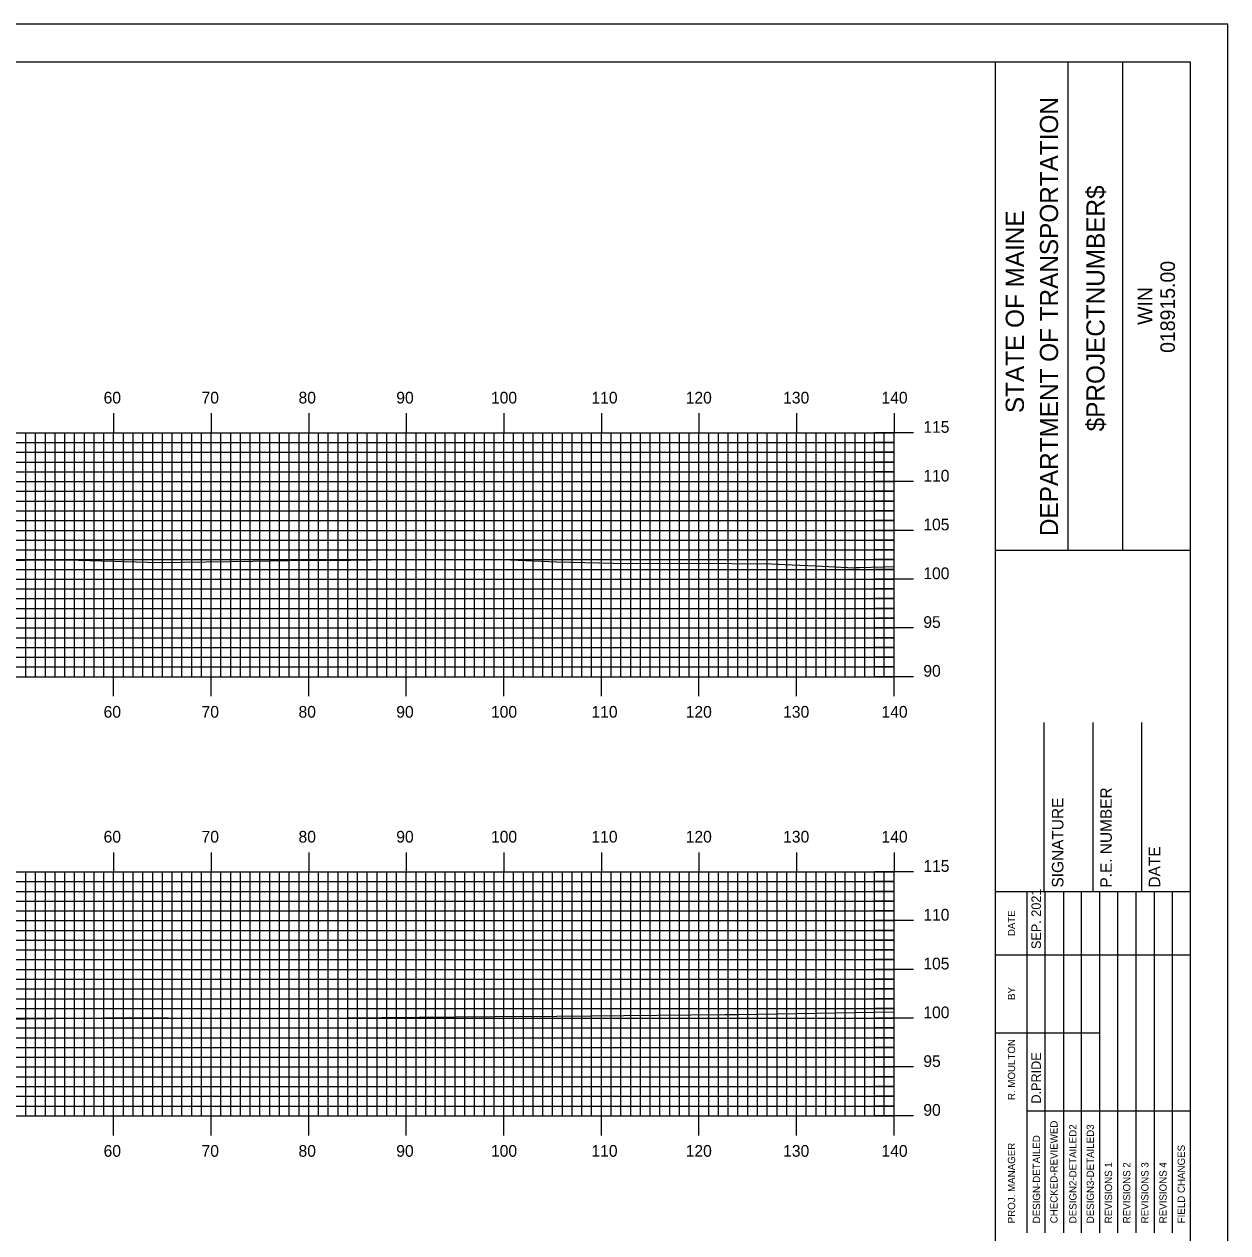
# Model space of a CAD drawing. Extents: x 1765333 to 1765676, y 442591 to 442811.
# Drawn here: x 1765549.2 to 1765672.6, y 442686.7 to 442810.5 of the extents above; entities that cross this region are included whole.
import ezdxf

# ---------------------------------------------------------------- set-up
doc = ezdxf.new("R2010")
doc.units = 0
for name, color, linetype in [('BORDER', 7, 'Continuous'), ('H_V ANNOTATION', 7, 'Continuous'), ('MAJOR', 7, 'Continuous'), ('MINOR', 7, 'Continuous'), ('PLOT BOUNDARY', 7, 'Continuous'), ('S_Roadway_Centerline', 7, 'Continuous')]:
    doc.layers.add(name, color=color, linetype=linetype)

msp = doc.modelspace()

# ---------------------------------------------------------------- linework, layer by layer
at = {"layer": 'BORDER'}
for p, q in [((1765648.77, 442596.67), (1765648.77, 442806.67)), ((1765656.23, 442756.66), (1765656.23, 442806.66)), ((1765661.82, 442756.66), (1765661.82, 442806.66)), ((1765648.77, 442756.65), (1765668.77, 442756.65)), ((1765653.77, 442721.67), (1765653.77, 442738.97)), ((1765658.77, 442721.67), (1765658.77, 442738.97)), ((1765663.77, 442721.67), (1765663.77, 442738.97)), ((1765648.77, 442721.67), (1765668.77, 442721.67))]:
    msp.add_line(p, q, dxfattribs=at)
msp.add_lwpolyline([(1765348.77, 442596.67), (1765668.77, 442596.67), (1765668.77, 442806.67), (1765348.77, 442806.67)], close=True, dxfattribs=at)
for points in [[(1765652, 442715.17), (1765652, 442721.67)], [(1765653.87, 442686.68), (1765653.87, 442721.67)], [(1765655.73, 442721.67), (1765655.73, 442686.68)], [(1765657.59, 442686.68), (1765657.59, 442721.67)], [(1765659.46, 442686.68), (1765659.46, 442721.67)], [(1765661.32, 442686.68), (1765661.32, 442721.67)], [(1765663.18, 442686.68), (1765663.18, 442721.67)], [(1765665.05, 442686.68), (1765665.05, 442721.67)], [(1765666.91, 442686.68), (1765666.91, 442721.67)], [(1765652, 442686.68), (1765652, 442720.26)], [(1765648.77, 442715.17), (1765668.77, 442715.17)], [(1765648.77, 442707.17), (1765652, 442707.17)], [(1765652, 442707.17), (1765659.45, 442707.17)], [(1765652, 442699.17), (1765668.77, 442699.17)]]:
    msp.add_lwpolyline(points, dxfattribs=at)
at = {"layer": 'MAJOR'}
for p, q in [((1765558.37, 442770.67), (1765558.37, 442768.67)), ((1765568.37, 442770.67), (1765568.37, 442768.67)), ((1765578.37, 442770.67), (1765578.37, 442768.67)), ((1765588.37, 442770.67), (1765588.37, 442768.67)), ((1765598.37, 442770.67), (1765598.37, 442768.67)), ((1765608.37, 442770.67), (1765608.37, 442768.67)), ((1765618.37, 442770.67), (1765618.37, 442768.67)), ((1765628.37, 442770.67), (1765628.37, 442768.67)), ((1765638.37, 442770.67), (1765638.37, 442768.67)), ((1765358.37, 442768.67), (1765638.37, 442768.67)), ((1765358.37, 442768.67), (1765638.37, 442768.67)), ((1765558.37, 442743.67), (1765558.37, 442768.67)), ((1765568.37, 442743.67), (1765568.37, 442768.67)), ((1765578.37, 442743.67), (1765578.37, 442768.67)), ((1765588.37, 442743.67), (1765588.37, 442768.67)), ((1765598.37, 442743.67), (1765598.37, 442768.67)), ((1765608.37, 442743.67), (1765608.37, 442768.67)), ((1765618.37, 442743.67), (1765618.37, 442768.67)), ((1765628.37, 442743.67), (1765628.37, 442768.67)), ((1765640.37, 442768.67), (1765636.37, 442768.67)), ((1765638.37, 442743.67), (1765638.37, 442768.67)), ((1765638.37, 442743.67), (1765638.37, 442768.67)), ((1765358.37, 442763.67), (1765638.37, 442763.67)), ((1765640.37, 442763.67), (1765636.37, 442763.67)), ((1765358.37, 442758.67), (1765638.37, 442758.67)), ((1765640.37, 442758.67), (1765636.37, 442758.67)), ((1765358.37, 442753.67), (1765638.37, 442753.67)), ((1765640.37, 442753.67), (1765636.37, 442753.67)), ((1765358.37, 442748.67), (1765638.37, 442748.67)), ((1765640.37, 442748.67), (1765636.37, 442748.67)), ((1765358.37, 442743.67), (1765638.37, 442743.67)), ((1765358.37, 442743.67), (1765638.37, 442743.67)), ((1765558.37, 442741.66), (1765558.37, 442743.67)), ((1765568.37, 442741.66), (1765568.37, 442743.67)), ((1765578.37, 442741.66), (1765578.37, 442743.67)), ((1765588.37, 442741.66), (1765588.37, 442743.67)), ((1765598.37, 442741.66), (1765598.37, 442743.67)), ((1765608.37, 442741.66), (1765608.37, 442743.67)), ((1765618.37, 442741.66), (1765618.37, 442743.67)), ((1765628.37, 442741.66), (1765628.37, 442743.67)), ((1765640.37, 442743.67), (1765636.37, 442743.67)), ((1765638.37, 442741.66), (1765638.37, 442743.67)), ((1765558.37, 442725.67), (1765558.37, 442723.67)), ((1765568.37, 442725.67), (1765568.37, 442723.67)), ((1765578.37, 442725.67), (1765578.37, 442723.67)), ((1765588.37, 442725.67), (1765588.37, 442723.67)), ((1765598.37, 442725.67), (1765598.37, 442723.67)), ((1765608.37, 442725.67), (1765608.37, 442723.67)), ((1765618.37, 442725.67), (1765618.37, 442723.67)), ((1765628.37, 442725.67), (1765628.37, 442723.67)), ((1765638.37, 442725.67), (1765638.37, 442723.67)), ((1765358.37, 442723.67), (1765638.37, 442723.67)), ((1765358.37, 442723.67), (1765638.37, 442723.67)), ((1765558.37, 442698.67), (1765558.37, 442723.67)), ((1765568.37, 442698.67), (1765568.37, 442723.67)), ((1765578.37, 442698.67), (1765578.37, 442723.67)), ((1765588.37, 442698.67), (1765588.37, 442723.67)), ((1765598.37, 442698.67), (1765598.37, 442723.67)), ((1765608.37, 442698.67), (1765608.37, 442723.67)), ((1765618.37, 442698.67), (1765618.37, 442723.67)), ((1765628.37, 442698.67), (1765628.37, 442723.67)), ((1765640.37, 442723.67), (1765636.37, 442723.67)), ((1765638.37, 442698.67), (1765638.37, 442723.67)), ((1765638.37, 442698.67), (1765638.37, 442723.67)), ((1765358.37, 442718.67), (1765638.37, 442718.67)), ((1765640.37, 442718.67), (1765636.37, 442718.67)), ((1765358.37, 442713.67), (1765638.37, 442713.67)), ((1765640.37, 442713.67), (1765636.37, 442713.67)), ((1765358.37, 442708.67), (1765638.37, 442708.67)), ((1765640.37, 442708.67), (1765636.37, 442708.67)), ((1765358.37, 442703.67), (1765638.37, 442703.67)), ((1765640.37, 442703.67), (1765636.37, 442703.67)), ((1765358.37, 442698.67), (1765638.37, 442698.67)), ((1765358.37, 442698.67), (1765638.37, 442698.67)), ((1765558.37, 442696.66), (1765558.37, 442698.67)), ((1765568.37, 442696.66), (1765568.37, 442698.67)), ((1765578.37, 442696.66), (1765578.37, 442698.67)), ((1765588.37, 442696.66), (1765588.37, 442698.67)), ((1765598.37, 442696.66), (1765598.37, 442698.67)), ((1765608.37, 442696.66), (1765608.37, 442698.67)), ((1765618.37, 442696.66), (1765618.37, 442698.67)), ((1765628.37, 442696.66), (1765628.37, 442698.67)), ((1765640.37, 442698.67), (1765636.37, 442698.67)), ((1765638.37, 442696.66), (1765638.37, 442698.67))]:
    msp.add_line(p, q, dxfattribs=at)
at = {"layer": 'MINOR'}
for p, q in [((1765549.37, 442743.67), (1765549.37, 442768.67)), ((1765550.37, 442743.67), (1765550.37, 442768.67)), ((1765551.37, 442743.67), (1765551.37, 442768.67)), ((1765552.37, 442743.67), (1765552.37, 442768.67)), ((1765553.37, 442743.67), (1765553.37, 442768.67)), ((1765554.37, 442743.67), (1765554.37, 442768.67)), ((1765555.37, 442743.67), (1765555.37, 442768.67)), ((1765556.37, 442743.67), (1765556.37, 442768.67)), ((1765557.37, 442743.67), (1765557.37, 442768.67)), ((1765559.37, 442743.67), (1765559.37, 442768.67)), ((1765560.37, 442743.67), (1765560.37, 442768.67)), ((1765561.37, 442743.67), (1765561.37, 442768.67)), ((1765562.37, 442743.67), (1765562.37, 442768.67)), ((1765563.37, 442743.67), (1765563.37, 442768.67)), ((1765564.37, 442743.67), (1765564.37, 442768.67)), ((1765565.37, 442743.67), (1765565.37, 442768.67)), ((1765566.37, 442743.67), (1765566.37, 442768.67)), ((1765567.37, 442743.67), (1765567.37, 442768.67)), ((1765569.37, 442743.67), (1765569.37, 442768.67)), ((1765570.37, 442743.67), (1765570.37, 442768.67)), ((1765571.37, 442743.67), (1765571.37, 442768.67)), ((1765572.37, 442743.67), (1765572.37, 442768.67)), ((1765573.37, 442743.67), (1765573.37, 442768.67)), ((1765574.37, 442743.67), (1765574.37, 442768.67)), ((1765575.37, 442743.67), (1765575.37, 442768.67)), ((1765576.37, 442743.67), (1765576.37, 442768.67)), ((1765577.37, 442743.67), (1765577.37, 442768.67)), ((1765579.37, 442743.67), (1765579.37, 442768.67)), ((1765580.37, 442743.67), (1765580.37, 442768.67)), ((1765581.37, 442743.67), (1765581.37, 442768.67)), ((1765582.37, 442743.67), (1765582.37, 442768.67)), ((1765583.37, 442743.67), (1765583.37, 442768.67)), ((1765584.37, 442743.67), (1765584.37, 442768.67)), ((1765585.37, 442743.67), (1765585.37, 442768.67)), ((1765586.37, 442743.67), (1765586.37, 442768.67)), ((1765587.37, 442743.67), (1765587.37, 442768.67)), ((1765589.37, 442743.67), (1765589.37, 442768.67)), ((1765590.37, 442743.67), (1765590.37, 442768.67)), ((1765591.37, 442743.67), (1765591.37, 442768.67)), ((1765592.37, 442743.67), (1765592.37, 442768.67)), ((1765593.37, 442743.67), (1765593.37, 442768.67)), ((1765594.37, 442743.67), (1765594.37, 442768.67)), ((1765595.37, 442743.67), (1765595.37, 442768.67)), ((1765596.37, 442743.67), (1765596.37, 442768.67)), ((1765597.37, 442743.67), (1765597.37, 442768.67)), ((1765599.37, 442743.67), (1765599.37, 442768.67)), ((1765600.37, 442743.67), (1765600.37, 442768.67)), ((1765601.37, 442743.67), (1765601.37, 442768.67)), ((1765602.37, 442743.67), (1765602.37, 442768.67)), ((1765603.37, 442743.67), (1765603.37, 442768.67)), ((1765604.37, 442743.67), (1765604.37, 442768.67)), ((1765605.37, 442743.67), (1765605.37, 442768.67)), ((1765606.37, 442743.67), (1765606.37, 442768.67)), ((1765607.37, 442743.67), (1765607.37, 442768.67)), ((1765609.37, 442743.67), (1765609.37, 442768.67)), ((1765610.37, 442743.67), (1765610.37, 442768.67)), ((1765611.37, 442743.67), (1765611.37, 442768.67)), ((1765612.37, 442743.67), (1765612.37, 442768.67)), ((1765613.37, 442743.67), (1765613.37, 442768.67)), ((1765614.37, 442743.67), (1765614.37, 442768.67)), ((1765615.37, 442743.67), (1765615.37, 442768.67)), ((1765616.37, 442743.67), (1765616.37, 442768.67)), ((1765617.37, 442743.67), (1765617.37, 442768.67)), ((1765619.37, 442743.67), (1765619.37, 442768.67)), ((1765620.37, 442743.67), (1765620.37, 442768.67)), ((1765621.37, 442743.67), (1765621.37, 442768.67)), ((1765622.37, 442743.67), (1765622.37, 442768.67)), ((1765623.37, 442743.67), (1765623.37, 442768.67)), ((1765624.37, 442743.67), (1765624.37, 442768.67)), ((1765625.37, 442743.67), (1765625.37, 442768.67)), ((1765626.37, 442743.67), (1765626.37, 442768.67)), ((1765627.37, 442743.67), (1765627.37, 442768.67)), ((1765629.37, 442743.67), (1765629.37, 442768.67)), ((1765630.37, 442743.67), (1765630.37, 442768.67)), ((1765631.37, 442743.67), (1765631.37, 442768.67)), ((1765632.37, 442743.67), (1765632.37, 442768.67)), ((1765633.37, 442743.67), (1765633.37, 442768.67)), ((1765634.37, 442743.67), (1765634.37, 442768.67)), ((1765635.37, 442743.67), (1765635.37, 442768.67)), ((1765636.37, 442743.67), (1765636.37, 442768.67)), ((1765637.37, 442743.67), (1765637.37, 442768.67)), ((1765358.37, 442767.67), (1765638.37, 442767.67)), ((1765638.37, 442767.67), (1765636.37, 442767.67)), ((1765358.37, 442766.67), (1765638.37, 442766.67)), ((1765638.37, 442766.67), (1765636.37, 442766.67)), ((1765358.37, 442765.67), (1765638.37, 442765.67)), ((1765638.37, 442765.67), (1765636.37, 442765.67)), ((1765358.37, 442764.67), (1765638.37, 442764.67)), ((1765638.37, 442764.67), (1765636.37, 442764.67)), ((1765358.37, 442762.67), (1765638.37, 442762.67)), ((1765638.37, 442762.67), (1765636.37, 442762.67)), ((1765358.37, 442761.67), (1765638.37, 442761.67)), ((1765638.37, 442761.67), (1765636.37, 442761.67)), ((1765358.37, 442760.67), (1765638.37, 442760.67)), ((1765638.37, 442760.67), (1765636.37, 442760.67)), ((1765358.37, 442759.67), (1765638.37, 442759.67)), ((1765638.37, 442759.67), (1765636.37, 442759.67)), ((1765358.37, 442757.67), (1765638.37, 442757.67)), ((1765638.37, 442757.67), (1765636.37, 442757.67)), ((1765358.37, 442756.67), (1765638.37, 442756.67)), ((1765638.37, 442756.67), (1765636.37, 442756.67)), ((1765358.37, 442755.67), (1765638.37, 442755.67)), ((1765638.37, 442755.67), (1765636.37, 442755.67)), ((1765358.37, 442754.67), (1765638.37, 442754.67)), ((1765638.37, 442754.67), (1765636.37, 442754.67)), ((1765358.37, 442752.67), (1765638.37, 442752.67)), ((1765638.37, 442752.67), (1765636.37, 442752.67)), ((1765358.37, 442751.67), (1765638.37, 442751.67)), ((1765638.37, 442751.67), (1765636.37, 442751.67)), ((1765358.37, 442750.67), (1765638.37, 442750.67)), ((1765638.37, 442750.67), (1765636.37, 442750.67)), ((1765358.37, 442749.67), (1765638.37, 442749.67)), ((1765638.37, 442749.67), (1765636.37, 442749.67)), ((1765358.37, 442747.67), (1765638.37, 442747.67)), ((1765638.37, 442747.67), (1765636.37, 442747.67)), ((1765358.37, 442746.67), (1765638.37, 442746.67)), ((1765638.37, 442746.67), (1765636.37, 442746.67)), ((1765358.37, 442745.67), (1765638.37, 442745.67)), ((1765638.37, 442745.67), (1765636.37, 442745.67)), ((1765358.37, 442744.67), (1765638.37, 442744.67)), ((1765638.37, 442744.67), (1765636.37, 442744.67)), ((1765549.37, 442698.67), (1765549.37, 442723.67)), ((1765550.37, 442698.67), (1765550.37, 442723.67)), ((1765551.37, 442698.67), (1765551.37, 442723.67)), ((1765552.37, 442698.67), (1765552.37, 442723.67)), ((1765553.37, 442698.67), (1765553.37, 442723.67)), ((1765554.37, 442698.67), (1765554.37, 442723.67)), ((1765555.37, 442698.67), (1765555.37, 442723.67)), ((1765556.37, 442698.67), (1765556.37, 442723.67)), ((1765557.37, 442698.67), (1765557.37, 442723.67)), ((1765559.37, 442698.67), (1765559.37, 442723.67)), ((1765560.37, 442698.67), (1765560.37, 442723.67)), ((1765561.37, 442698.67), (1765561.37, 442723.67)), ((1765562.37, 442698.67), (1765562.37, 442723.67)), ((1765563.37, 442698.67), (1765563.37, 442723.67)), ((1765564.37, 442698.67), (1765564.37, 442723.67)), ((1765565.37, 442698.67), (1765565.37, 442723.67)), ((1765566.37, 442698.67), (1765566.37, 442723.67)), ((1765567.37, 442698.67), (1765567.37, 442723.67)), ((1765569.37, 442698.67), (1765569.37, 442723.67)), ((1765570.37, 442698.67), (1765570.37, 442723.67)), ((1765571.37, 442698.67), (1765571.37, 442723.67)), ((1765572.37, 442698.67), (1765572.37, 442723.67)), ((1765573.37, 442698.67), (1765573.37, 442723.67)), ((1765574.37, 442698.67), (1765574.37, 442723.67)), ((1765575.37, 442698.67), (1765575.37, 442723.67)), ((1765576.37, 442698.67), (1765576.37, 442723.67)), ((1765577.37, 442698.67), (1765577.37, 442723.67)), ((1765579.37, 442698.67), (1765579.37, 442723.67)), ((1765580.37, 442698.67), (1765580.37, 442723.67)), ((1765581.37, 442698.67), (1765581.37, 442723.67)), ((1765582.37, 442698.67), (1765582.37, 442723.67)), ((1765583.37, 442698.67), (1765583.37, 442723.67)), ((1765584.37, 442698.67), (1765584.37, 442723.67)), ((1765585.37, 442698.67), (1765585.37, 442723.67)), ((1765586.37, 442698.67), (1765586.37, 442723.67)), ((1765587.37, 442698.67), (1765587.37, 442723.67)), ((1765589.37, 442698.67), (1765589.37, 442723.67)), ((1765590.37, 442698.67), (1765590.37, 442723.67)), ((1765591.37, 442698.67), (1765591.37, 442723.67)), ((1765592.37, 442698.67), (1765592.37, 442723.67)), ((1765593.37, 442698.67), (1765593.37, 442723.67)), ((1765594.37, 442698.67), (1765594.37, 442723.67)), ((1765595.37, 442698.67), (1765595.37, 442723.67)), ((1765596.37, 442698.67), (1765596.37, 442723.67)), ((1765597.37, 442698.67), (1765597.37, 442723.67)), ((1765599.37, 442698.67), (1765599.37, 442723.67)), ((1765600.37, 442698.67), (1765600.37, 442723.67)), ((1765601.37, 442698.67), (1765601.37, 442723.67)), ((1765602.37, 442698.67), (1765602.37, 442723.67)), ((1765603.37, 442698.67), (1765603.37, 442723.67)), ((1765604.37, 442698.67), (1765604.37, 442723.67)), ((1765605.37, 442698.67), (1765605.37, 442723.67)), ((1765606.37, 442698.67), (1765606.37, 442723.67)), ((1765607.37, 442698.67), (1765607.37, 442723.67)), ((1765609.37, 442698.67), (1765609.37, 442723.67)), ((1765610.37, 442698.67), (1765610.37, 442723.67)), ((1765611.37, 442698.67), (1765611.37, 442723.67)), ((1765612.37, 442698.67), (1765612.37, 442723.67)), ((1765613.37, 442698.67), (1765613.37, 442723.67)), ((1765614.37, 442698.67), (1765614.37, 442723.67)), ((1765615.37, 442698.67), (1765615.37, 442723.67)), ((1765616.37, 442698.67), (1765616.37, 442723.67)), ((1765617.37, 442698.67), (1765617.37, 442723.67)), ((1765619.37, 442698.67), (1765619.37, 442723.67)), ((1765620.37, 442698.67), (1765620.37, 442723.67)), ((1765621.37, 442698.67), (1765621.37, 442723.67)), ((1765622.37, 442698.67), (1765622.37, 442723.67)), ((1765623.37, 442698.67), (1765623.37, 442723.67)), ((1765624.37, 442698.67), (1765624.37, 442723.67)), ((1765625.37, 442698.67), (1765625.37, 442723.67)), ((1765626.37, 442698.67), (1765626.37, 442723.67)), ((1765627.37, 442698.67), (1765627.37, 442723.67)), ((1765629.37, 442698.67), (1765629.37, 442723.67)), ((1765630.37, 442698.67), (1765630.37, 442723.67)), ((1765631.37, 442698.67), (1765631.37, 442723.67)), ((1765632.37, 442698.67), (1765632.37, 442723.67)), ((1765633.37, 442698.67), (1765633.37, 442723.67)), ((1765634.37, 442698.67), (1765634.37, 442723.67)), ((1765635.37, 442698.67), (1765635.37, 442723.67)), ((1765636.37, 442698.67), (1765636.37, 442723.67)), ((1765637.37, 442698.67), (1765637.37, 442723.67)), ((1765358.37, 442722.67), (1765638.37, 442722.67)), ((1765358.37, 442721.67), (1765638.37, 442721.67)), ((1765638.37, 442722.67), (1765636.37, 442722.67)), ((1765638.37, 442721.67), (1765636.37, 442721.67)), ((1765358.37, 442720.67), (1765638.37, 442720.67)), ((1765638.37, 442720.67), (1765636.37, 442720.67)), ((1765358.37, 442719.67), (1765638.37, 442719.67)), ((1765638.37, 442719.67), (1765636.37, 442719.67)), ((1765358.37, 442717.67), (1765638.37, 442717.67)), ((1765358.37, 442716.67), (1765638.37, 442716.67)), ((1765638.37, 442717.67), (1765636.37, 442717.67)), ((1765638.37, 442716.67), (1765636.37, 442716.67)), ((1765358.37, 442715.67), (1765638.37, 442715.67)), ((1765638.37, 442715.67), (1765636.37, 442715.67)), ((1765358.37, 442714.67), (1765638.37, 442714.67)), ((1765638.37, 442714.67), (1765636.37, 442714.67)), ((1765358.37, 442712.67), (1765638.37, 442712.67)), ((1765358.37, 442711.67), (1765638.37, 442711.67)), ((1765638.37, 442712.67), (1765636.37, 442712.67)), ((1765638.37, 442711.67), (1765636.37, 442711.67)), ((1765358.37, 442710.67), (1765638.37, 442710.67)), ((1765638.37, 442710.67), (1765636.37, 442710.67)), ((1765358.37, 442709.67), (1765638.37, 442709.67)), ((1765638.37, 442709.67), (1765636.37, 442709.67)), ((1765358.37, 442707.67), (1765638.37, 442707.67)), ((1765358.37, 442706.67), (1765638.37, 442706.67)), ((1765638.37, 442707.67), (1765636.37, 442707.67)), ((1765638.37, 442706.67), (1765636.37, 442706.67)), ((1765358.37, 442705.67), (1765638.37, 442705.67)), ((1765638.37, 442705.67), (1765636.37, 442705.67)), ((1765358.37, 442704.67), (1765638.37, 442704.67)), ((1765638.37, 442704.67), (1765636.37, 442704.67)), ((1765358.37, 442702.67), (1765638.37, 442702.67)), ((1765358.37, 442701.67), (1765638.37, 442701.67)), ((1765638.37, 442702.67), (1765636.37, 442702.67)), ((1765638.37, 442701.67), (1765636.37, 442701.67)), ((1765358.37, 442700.67), (1765638.37, 442700.67)), ((1765638.37, 442700.67), (1765636.37, 442700.67)), ((1765358.37, 442699.67), (1765638.37, 442699.67)), ((1765638.37, 442699.67), (1765636.37, 442699.67))]:
    msp.add_line(p, q, dxfattribs=at)
at = {"layer": 'PLOT BOUNDARY'}
msp.add_lwpolyline([(1765332.58, 442590.55), (1765672.58, 442590.55), (1765672.58, 442810.55), (1765332.58, 442810.55)], close=True, dxfattribs=at)
at = {"layer": 'S_Roadway_Centerline'}
for points in [[(1765544.97, 442755.57), (1765553.57, 442755.65), (1765563.03, 442755.39), (1765572.63, 442755.5), (1765578.13, 442755.61), (1765580.58, 442755.59), (1765586.84, 442755.68), (1765599.06, 442755.64), (1765603.75, 442755.45), (1765611.04, 442755.27), (1765617.63, 442755.3), (1765625.8, 442755.25), (1765627.93, 442755.14), (1765630.31, 442755.03), (1765632.32, 442754.93), (1765634.21, 442754.83), (1765634.49, 442754.85), (1765634.84, 442754.85), (1765637.24, 442754.93), (1765638.37, 442754.97)], [(1765547.39, 442708.62), (1765549.41, 442708.6), (1765560.04, 442708.73), (1765567.98, 442708.68), (1765582.42, 442708.72), (1765585.86, 442708.75), (1765597.3, 442708.83), (1765603.8, 442708.87), (1765620.98, 442709.04), (1765621.64, 442709.05), (1765621.89, 442709.05), (1765622.43, 442709.06), (1765638.37, 442709.31)]]:
    msp.add_lwpolyline(points, dxfattribs=at)

# ---------------------------------------------------------------- texts
at = {"layer": 'BORDER'}
for s, height, p in [('DEPARTMENT OF TRANSPORTATION', 1.8635, (1765655.18, 442758.08)), ('$PROJECTNUMBER$', 1.8635, (1765659.95, 442768.82)), ('STATE OF MAINE', 1.8635, (1765651.68, 442770.69)), ('018915.00', 1.491, (1765667.16, 442776.86)), ('WIN', 1.491, (1765664.84, 442779.73)), ('P.E. NUMBER', 1.1811, (1765660.69, 442722.06)), ('SIGNATURE', 1.181, (1765655.73, 442722.06)), ('DATE', 1.181, (1765665.65, 442722.06)), ('SEP. 2021', 0.969, (1765653.42, 442715.76)), ('DATE', 0.743, (1765650.78, 442717.08)), ('BY', 0.743, (1765650.78, 442710.54)), ('R. MOULTON', 0.745, (1765650.78, 442700.28)), ('D.PRIDE', 0.969, (1765653.42, 442699.92)), ('CHECKED-REVIEWED', 0.7455, (1765655.13, 442687.65)), ('DESIGN2-DETAILED2', 0.7455, (1765657.07, 442687.65)), ('DESIGN3-DETAILED3', 0.7455, (1765658.86, 442687.65)), ('PROJ. MANAGER', 0.7455, (1765650.78, 442687.65)), ('DESIGN-DETAILED', 0.7455, (1765653.34, 442687.65)), ('FIELD CHANGES', 0.7455, (1765668.18, 442687.65)), ('REVISIONS 1', 0.7455, (1765660.72, 442687.65)), ('REVISIONS 2', 0.7455, (1765662.59, 442687.65)), ('REVISIONS 3', 0.7455, (1765664.45, 442687.65)), ('REVISIONS 4', 0.7455, (1765666.31, 442687.65))]:
    msp.add_text(s, height=height, rotation=90, dxfattribs=at).set_placement(p)
at = {"layer": 'H_V ANNOTATION'}
for s, p in [('60', (1765557.34, 442771.67)), ('70', (1765567.38, 442771.67)), ('80', (1765577.32, 442771.67)), ('90', (1765587.34, 442771.67)), ('100', (1765597.05, 442771.67)), ('110', (1765607.35, 442771.67)), ('120', (1765617.01, 442771.67)), ('130', (1765627, 442771.67)), ('140', (1765637.08, 442771.67)), ('115', (1765641.37, 442768.67)), ('110', (1765641.37, 442763.67)), ('105', (1765641.37, 442758.67)), ('100', (1765641.37, 442753.67)), ('95', (1765641.37, 442748.67)), ('90', (1765641.37, 442743.67)), ('60', (1765557.34, 442739.47)), ('70', (1765567.38, 442739.47)), ('80', (1765577.32, 442739.47)), ('90', (1765587.34, 442739.47)), ('100', (1765597.05, 442739.47)), ('110', (1765607.35, 442739.47)), ('120', (1765617.01, 442739.47)), ('130', (1765627, 442739.47)), ('140', (1765637.08, 442739.47)), ('60', (1765557.34, 442726.67)), ('70', (1765567.38, 442726.67)), ('80', (1765577.32, 442726.67)), ('90', (1765587.34, 442726.67)), ('100', (1765597.05, 442726.67)), ('110', (1765607.35, 442726.67)), ('120', (1765617.01, 442726.67)), ('130', (1765627, 442726.67)), ('140', (1765637.08, 442726.67)), ('115', (1765641.37, 442723.67)), ('110', (1765641.37, 442718.67)), ('105', (1765641.37, 442713.67)), ('100', (1765641.37, 442708.67)), ('95', (1765641.37, 442703.67)), ('90', (1765641.37, 442698.67)), ('60', (1765557.34, 442694.47)), ('70', (1765567.38, 442694.47)), ('80', (1765577.32, 442694.47)), ('90', (1765587.34, 442694.47)), ('100', (1765597.05, 442694.47)), ('110', (1765607.35, 442694.47)), ('120', (1765617.01, 442694.47)), ('130', (1765627, 442694.47)), ('140', (1765637.08, 442694.47))]:
    msp.add_text(s, height=1.2, dxfattribs=at).set_placement(p)

doc.saveas('drawing.dxf')
